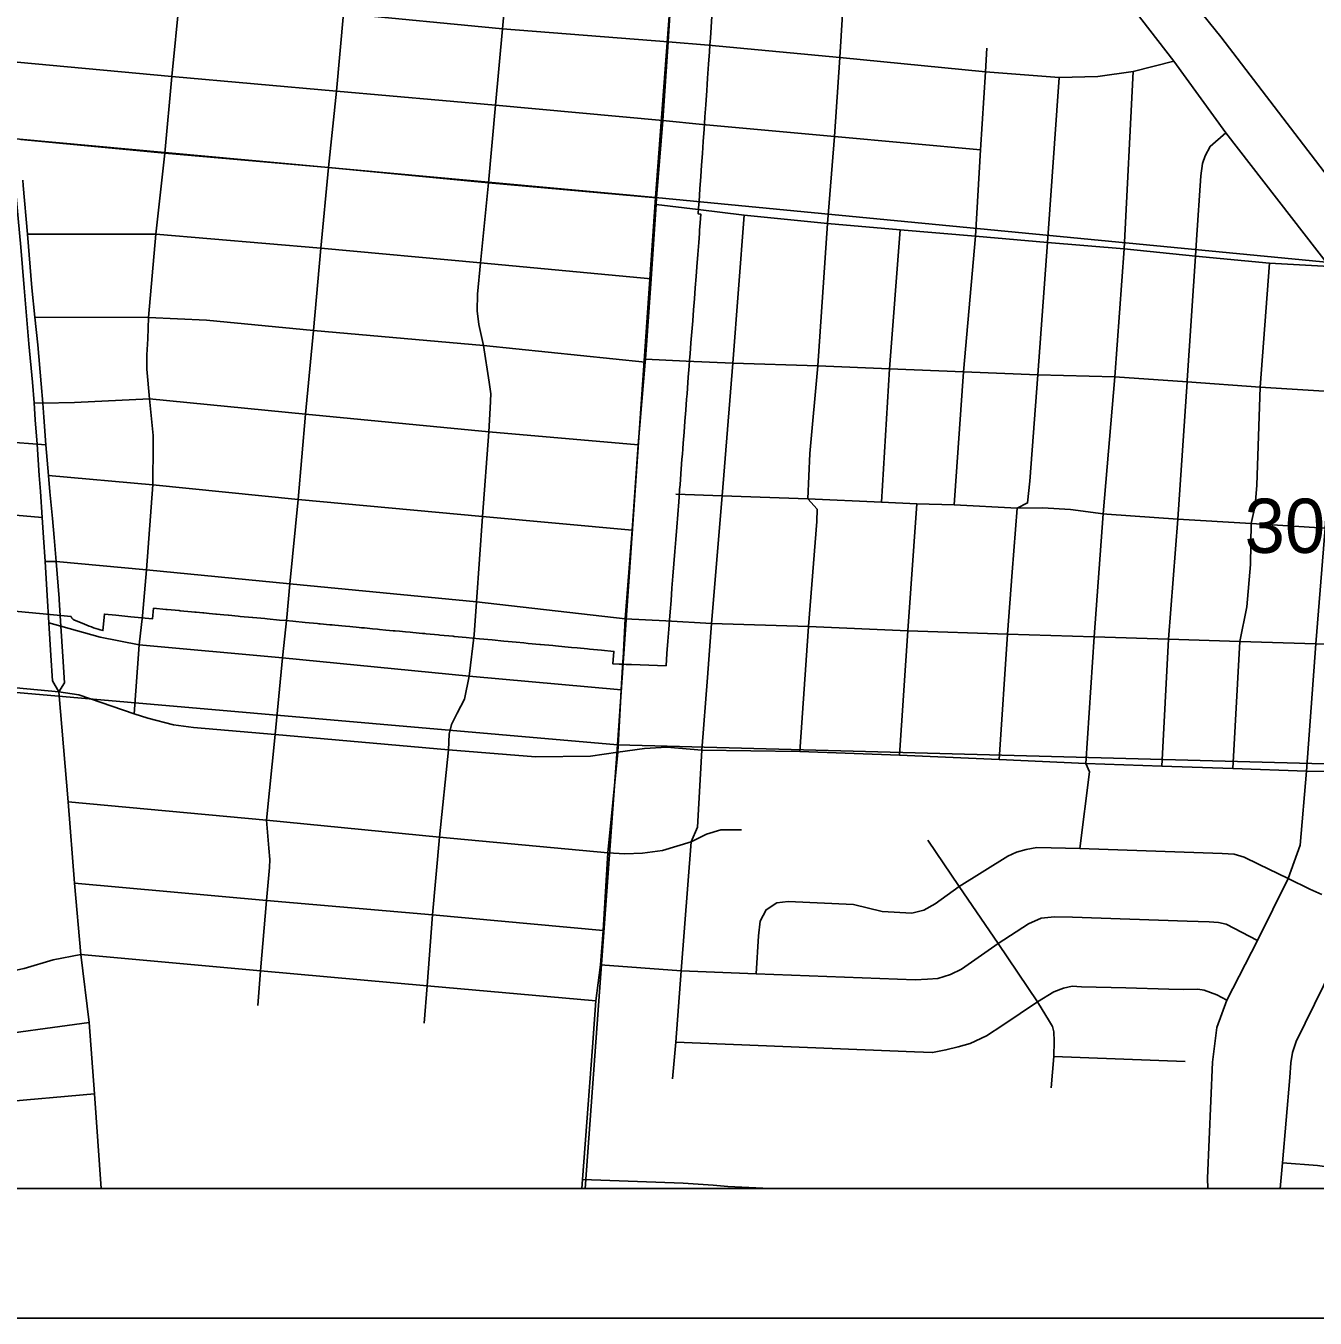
# Model space of a CAD drawing. Extents: x 0 to 34, y 0 to 22.
# Drawn here: x 7.342 to 8.337, y 14 to 14.998 of the extents above; entities that cross this region are included whole.
import ezdxf

# ---------------------------------------------------------------- set-up
doc = ezdxf.new("R2010")
doc.units = 0
for name, color, linetype in [('Default', 7, 'Continuous'), ('GM_X_City_Street', 7, 'Continuous'), ('GM_X_Corporation', 7, 'Continuous'), ('GM_X_Rail_Line', 7, 'Continuous'), ('GM_X_Section', 7, 'Continuous'), ('GM_X_Section_Text', 7, 'Continuous'), ('GM_X_State_Route', 7, 'Continuous'), ('GM_X_Township_Road', 7, 'Continuous'), ('SH_Data', 7, 'Continuous')]:
    doc.layers.add(name, color=color, linetype=linetype)

msp = doc.modelspace()

# ---------------------------------------------------------------- linework, layer by layer
at = {"layer": 'Default'}
for points in [[(8.9, 15.6028), (8.9, 15.78137), (7.90346, 15.87364), (7.82775, 14.86502), (8.83407, 14.76814)], [(6.72325, 14.1), (7.77344, 14.1), (7.79825, 14.44254), (6.76074, 14.53281), (6.76045, 14.51691)], [(7.77344, 14.1), (8.79639, 14.1), (8.82252, 14.41502), (7.79825, 14.44254)]]:
    msp.add_lwpolyline(points, close=True, dxfattribs=at)
at = {"layer": 'GM_X_City_Street'}
for p, q in [((7.8282, 14.85973), (7.86053, 14.85582)), ((7.34276, 14.83673), (7.37219, 14.83675)), ((7.81996, 14.74034), (7.85134, 14.73881)), ((8.1353, 14.20188), (8.23659, 14.19801)), ((7.26588, 14.16169), (7.39451, 14.17313))]:
    msp.add_line(p, q, dxfattribs=at)
for points in [[(7.80248, 14.50741), (7.8026, 14.50944), (7.80419, 14.53992), (7.80967, 14.60835), (7.81431, 14.67421), (7.81979, 14.73808), (7.81996, 14.74034), (7.82422, 14.80234), (7.8282, 14.85973), (7.82851, 14.86492), (7.83323, 14.92441), (7.83738, 14.98531), (7.84122, 15.04775), (7.84541, 15.10967), (7.85043, 15.17176), (7.85477, 15.23687), (7.86017, 15.30105), (7.86443, 15.36461), (7.86956, 15.42929), (7.87493, 15.48931), (7.87753, 15.51728)], [(7.93914, 14.43752), (7.94569, 14.53392), (7.95226, 14.61493), (7.95238, 14.62456), (7.94521, 14.63248), (7.94669, 14.66746), (7.95296, 14.73502), (7.96055, 14.8451), (7.96582, 14.91219), (7.96987, 14.97313), (7.97374, 15.03613), (7.97806, 15.09848), (7.98222, 15.16109), (7.98638, 15.22522), (7.99124, 15.26922), (7.99013, 15.27644), (7.97875, 15.29004), (7.92809, 15.36168)], [(8.44445, 14.41972), (8.451, 14.51656), (8.45794, 14.60152), (8.46058, 14.63262), (8.46002, 14.64178), (8.45781, 14.65066), (8.45392, 14.65899), (8.44656, 14.67093), (8.4168, 14.71819), (8.41047, 14.72742), (8.38701, 14.76102), (8.36285, 14.79392), (8.34798, 14.81194), (8.26805, 14.9151), (8.22792, 14.97021), (8.17045, 15.04462), (8.13972, 15.08425), (8.07356, 15.17136), (8.03941, 15.21703), (8.03261, 15.22771), (8.02817, 15.23813)], [(7.68756, 14.52761), (7.68949, 14.55294), (7.69418, 14.61878), (7.69893, 14.68431), (7.70014, 14.7025), (7.70057, 14.71355), (7.69927, 14.72257), (7.69491, 14.75076), (7.69118, 14.76702), (7.6901, 14.77766), (7.69025, 14.79044), (7.69258, 14.81472), (7.69868, 14.8765), (7.70421, 14.93624), (7.70959, 14.99525), (7.71526, 15.05775)], [(7.3291, 15.03094), (7.46012, 15.01847), (7.58683, 15.00705), (7.70959, 14.99525), (7.83738, 14.98531), (7.86862, 14.98272)], [(7.43159, 14.54219), (7.43472, 14.57776), (7.4395, 14.64325), (7.43978, 14.67471), (7.43983, 14.68129), (7.43712, 14.70967), (7.43498, 14.73253), (7.43489, 14.74356), (7.4356, 14.75609), (7.43627, 14.77249), (7.44185, 14.8368), (7.44885, 14.89925), (7.45437, 14.95858), (7.46012, 15.01847)], [(7.54291, 14.54077), (7.54529, 14.56689), (7.55185, 14.63199), (7.55747, 14.69793), (7.5636, 14.76251), (7.56928, 14.82608), (7.57526, 14.88819), (7.58146, 14.94729), (7.58683, 15.00705)], [(7.86862, 14.98272), (7.96987, 14.97313), (8.08245, 14.96216), (8.13922, 14.95773), (8.1692, 14.95841), (8.19655, 14.96244), (8.22792, 14.97021)], [(8.0583, 14.62791), (8.06537, 14.73062), (8.07481, 14.83512), (8.07856, 14.90178), (8.08245, 14.96216), (8.08342, 14.98048)], [(7.33473, 14.96963), (7.45437, 14.95858), (7.58146, 14.94729), (7.70421, 14.93624), (7.83323, 14.92441), (7.86384, 14.92148)], [(8.09288, 14.43134), (8.09938, 14.52808), (8.10299, 14.57584), (8.10686, 14.62534), (8.11493, 14.62928), (8.11659, 14.64622), (8.12284, 14.72825), (8.13036, 14.83045), (8.13922, 14.95773)], [(8.1552, 14.36244), (8.16265, 14.42185), (8.15985, 14.42807), (8.16629, 14.526), (8.17323, 14.62095), (8.18233, 14.72665), (8.18955, 14.8255), (8.19655, 14.96244)], [(7.86384, 14.92148), (7.96582, 14.91219), (8.07856, 14.90178)], [(8.21853, 14.42605), (8.22362, 14.5242), (8.23094, 14.61688), (8.238, 14.72285), (8.23807, 14.7239), (8.24446, 14.81984), (8.24529, 14.83241), (8.24873, 14.8818), (8.25003, 14.89128), (8.25202, 14.89733), (8.25593, 14.90449), (8.26805, 14.9151)], [(7.33779, 14.90977), (7.44885, 14.89925), (7.57526, 14.88819), (7.69868, 14.8765), (7.82851, 14.86492)], [(7.86053, 14.85582), (7.89618, 14.85146), (7.96055, 14.8451), (8.01664, 14.84008), (8.07481, 14.83512), (8.13036, 14.83045), (8.18955, 14.8255), (8.24446, 14.81984), (8.30164, 14.81445), (8.34798, 14.81194)], [(7.84082, 14.18468), (7.84344, 14.2131), (7.84738, 14.26806), (7.85518, 14.36757), (7.86007, 14.37911), (7.86355, 14.43838), (7.86793, 14.49462), (7.871, 14.53617), (7.87909, 14.63467), (7.88731, 14.73728), (7.89618, 14.85146)], [(7.37219, 14.83675), (7.44185, 14.8368), (7.56928, 14.82608), (7.69258, 14.81472), (7.82422, 14.80234)], [(8.00221, 14.62984), (8.00835, 14.73274), (8.01664, 14.84008)], [(8.27346, 14.42418), (8.27887, 14.52239), (8.28412, 14.54913), (8.28692, 14.5818), (8.28748, 14.61332), (8.29068, 14.62738), (8.29201, 14.6431), (8.29456, 14.71868), (8.30164, 14.81445)], [(8.33026, 14.42217), (8.33734, 14.52058), (8.34457, 14.60971), (8.35202, 14.71503), (8.35634, 14.76699), (8.35719, 14.78684), (8.35845, 14.78914), (8.36285, 14.79392)], [(7.34854, 14.77272), (7.43627, 14.77249), (7.4809, 14.77032), (7.5636, 14.76251), (7.69491, 14.75076), (7.81979, 14.73808)], [(7.85134, 14.73881), (7.88731, 14.73728), (7.95296, 14.73502), (8.00835, 14.73274), (8.06537, 14.73062), (8.12284, 14.72825), (8.18233, 14.72665), (8.238, 14.72285), (8.29456, 14.71868), (8.35202, 14.71503), (8.40756, 14.71299), (8.4168, 14.71819)], [(7.15465, 14.71039), (7.17396, 14.69747), (7.18437, 14.69271), (7.19427, 14.68932), (7.20744, 14.68631), (7.28905, 14.67941), (7.35032, 14.67462), (7.35688, 14.67411)], [(7.34802, 14.7065), (7.35464, 14.70645), (7.37916, 14.70681), (7.43712, 14.70967), (7.55747, 14.69793), (7.69893, 14.68431), (7.81431, 14.67421)], [(7.0696, 14.67518), (7.08051, 14.67263), (7.10461, 14.66403), (7.12338, 14.65579), (7.13702, 14.64782), (7.14746, 14.64269), (7.16434, 14.63613), (7.17764, 14.6339), (7.29483, 14.62324), (7.35419, 14.61804)], [(6.28784, 14.66728), (6.34893, 14.6487), (6.45161, 14.61893), (6.52667, 14.59923), (6.6213, 14.57436), (6.68486, 14.55652), (6.71161, 14.54761), (6.73821, 14.53567), (6.77373, 14.51453), (6.8255, 14.48246), (6.83873, 14.47599), (6.85613, 14.47081), (6.87641, 14.4688), (6.89223, 14.46894), (6.90273, 14.47081), (6.94645, 14.48218), (7.0132, 14.49983), (7.05128, 14.50431), (7.10536, 14.50327), (7.11039, 14.50312), (7.15983, 14.50073), (7.24783, 14.4934), (7.29805, 14.48994), (7.36696, 14.48349)], [(7.35905, 14.65061), (7.4395, 14.64325), (7.55185, 14.63199), (7.69418, 14.61878), (7.80967, 14.60835)], [(7.84326, 14.63595), (7.87909, 14.63467), (7.94521, 14.63248), (8.00221, 14.62984), (8.02942, 14.62859), (8.0583, 14.62791), (8.10686, 14.62534), (8.12645, 14.6254), (8.14811, 14.62428), (8.17323, 14.62095), (8.17622, 14.62074)], [(8.01608, 14.43465), (8.02248, 14.53059), (8.02942, 14.62859)], [(8.17622, 14.62074), (8.23094, 14.61688), (8.28748, 14.61332), (8.34457, 14.60971), (8.40117, 14.6061), (8.45794, 14.60152)], [(7.35652, 14.58408), (7.36498, 14.58406), (7.43472, 14.57776), (7.54529, 14.56689), (7.68949, 14.55294), (7.80419, 14.53992), (7.8356, 14.53829)], [(7.35919, 14.53675), (7.36865, 14.53412), (7.39892, 14.52568), (7.42903, 14.51972), (7.53969, 14.50972), (7.6838, 14.4955), (7.8012, 14.48504)], [(7.42529, 14.46657), (7.42903, 14.51972), (7.43159, 14.54219)], [(7.52074, 14.24131), (7.52263, 14.26814), (7.52744, 14.32237), (7.52977, 14.34789), (7.52992, 14.35401), (7.52919, 14.36276), (7.52729, 14.38448), (7.53413, 14.45062), (7.53969, 14.50972), (7.54291, 14.54077)], [(7.8356, 14.53829), (7.871, 14.53617), (7.94569, 14.53392), (8.02248, 14.53059), (8.09938, 14.52808), (8.16629, 14.526), (8.22362, 14.5242), (8.27887, 14.52239), (8.33734, 14.52058), (8.39508, 14.5182), (8.451, 14.51656)], [(7.64911, 14.22768), (7.65136, 14.25648), (7.65552, 14.31129), (7.66099, 14.37136), (7.66793, 14.43873), (7.66835, 14.45074), (7.6701, 14.45832), (7.67447, 14.46693), (7.68029, 14.47772), (7.6838, 14.4955), (7.68756, 14.52761)], [(7.7709, 14.1), (7.77134, 14.10712), (7.77893, 14.20921), (7.78162, 14.24488), (7.78517, 14.27282), (7.78714, 14.29934), (7.79088, 14.35926), (7.79868, 14.437), (7.8012, 14.48504), (7.80248, 14.50741)], [(7.36696, 14.48349), (7.38247, 14.48117), (7.42529, 14.46657), (7.43582, 14.46312), (7.45545, 14.45809), (7.47101, 14.45602), (7.53413, 14.45062), (7.66793, 14.43873), (7.73504, 14.43324), (7.77736, 14.43378), (7.79868, 14.437), (7.81921, 14.43982), (7.83647, 14.44083), (7.86355, 14.43838), (7.93914, 14.43752), (8.01608, 14.43465), (8.09288, 14.43134), (8.15985, 14.42807), (8.21853, 14.42605), (8.27346, 14.42418), (8.33026, 14.42217), (8.38727, 14.42121)], [(8.254, 14.1), (8.25371, 14.10816), (8.25761, 14.19764), (8.26105, 14.22448), (8.26885, 14.24559), (8.29246, 14.29148), (8.31611, 14.33944), (8.32529, 14.36513), (8.33026, 14.42217)], [(7.37427, 14.39866), (7.52729, 14.38448), (7.66099, 14.37136), (7.79088, 14.35926), (7.80407, 14.35839), (7.81764, 14.3589), (7.83316, 14.36101), (7.85518, 14.36757), (7.86699, 14.37369), (7.87821, 14.3769), (7.89396, 14.3769)], [(8.13313, 14.17792), (8.1353, 14.20188), (8.13545, 14.21393), (8.1353, 14.22103), (8.13414, 14.22505), (8.1319, 14.2291), (8.12247, 14.24429), (8.09227, 14.2891), (8.06214, 14.33314), (8.03803, 14.36899)], [(7.90538, 14.26567), (7.90708, 14.29516), (7.90842, 14.30654), (7.91307, 14.31531), (7.9213, 14.32051), (7.93006, 14.32174), (7.98049, 14.31941), (8.00255, 14.31393), (8.02557, 14.3127), (8.03489, 14.31503), (8.04352, 14.31983), (8.06214, 14.33314), (8.09956, 14.35669), (8.10641, 14.3597), (8.11395, 14.36176), (8.12204, 14.36326), (8.1552, 14.36244), (8.26522, 14.3586), (8.27441, 14.35806), (8.28211, 14.35585), (8.29318, 14.35052), (8.31611, 14.33944), (8.33292, 14.33107), (8.34196, 14.32695)], [(6.95974, 14.35435), (7.00345, 14.33709), (7.0222, 14.32622), (7.02923, 14.32059), (7.0341, 14.31415), (7.03917, 14.30746), (7.0463, 14.30146), (7.05324, 14.29733), (7.06169, 14.29433), (7.07303, 14.29321), (7.10388, 14.29208), (7.11448, 14.29133), (7.12705, 14.28899), (7.13774, 14.28617), (7.15369, 14.28157), (7.17936, 14.2713), (7.20653, 14.26364), (7.23012, 14.25982), (7.26407, 14.25907), (7.30927, 14.26357), (7.34022, 14.26995), (7.36254, 14.27651), (7.3839, 14.2808)], [(7.37917, 14.33579), (7.52744, 14.32237), (7.65552, 14.31129), (7.78714, 14.29934)], [(8.30992, 14.1), (8.31168, 14.11991), (8.31743, 14.18582), (8.31812, 14.19719), (8.31935, 14.205), (8.32223, 14.2135), (8.36457, 14.29941), (8.36813, 14.32284)], [(7.78517, 14.27282), (7.84738, 14.26806), (7.90538, 14.26567), (8.02818, 14.26122), (8.03764, 14.2616), (8.04567, 14.26217), (8.05551, 14.26519), (8.06391, 14.26938), (8.09227, 14.2891), (8.11563, 14.30442), (8.12546, 14.30868), (8.13576, 14.30991), (8.14957, 14.30953), (8.23805, 14.3065), (8.25498, 14.30594), (8.26225, 14.30537), (8.26821, 14.30423), (8.29246, 14.29148)], [(7.3839, 14.2808), (7.52263, 14.26814), (7.65136, 14.25648), (7.78162, 14.24488)], [(7.84344, 14.2131), (8.0276, 14.20551), (8.04151, 14.20505), (8.05186, 14.20705), (8.06144, 14.20937), (8.07056, 14.21207), (8.08315, 14.21795), (8.09574, 14.22629), (8.12247, 14.24429), (8.13507, 14.25187), (8.14256, 14.25472), (8.14944, 14.25626), (8.15647, 14.25588), (8.19077, 14.25503), (8.22384, 14.25387), (8.23496, 14.25372), (8.2464, 14.25395), (8.25119, 14.25318), (8.261, 14.24947), (8.26885, 14.24559)], [(6.97034, 14.2325), (6.99724, 14.21666), (7.01866, 14.20941), (7.0267, 14.20815), (7.04583, 14.20784), (7.0741, 14.20862), (7.09969, 14.20902), (7.12662, 14.20752), (7.14662, 14.20571), (7.16559, 14.20146), (7.20224, 14.19501), (7.23115, 14.19182), (7.24672, 14.19117), (7.25666, 14.19201), (7.26023, 14.19276), (7.26276, 14.19492), (7.26848, 14.20111), (7.27185, 14.20683), (7.27401, 14.20964), (7.27786, 14.21152), (7.28836, 14.21443), (7.30356, 14.21649), (7.39034, 14.22813)], [(8.31168, 14.11991), (8.33881, 14.11772), (8.35155, 14.11593), (8.3606, 14.11319), (8.3717, 14.10744), (8.38708, 14.1)], [(7.77134, 14.10712), (7.84897, 14.10422), (7.8723, 14.10254)], [(7.8723, 14.10254), (7.88346, 14.10174), (7.91599, 14.1)]]:
    msp.add_lwpolyline(points, dxfattribs=at)
at = {"layer": 'GM_X_Corporation'}
msp.add_lwpolyline([(7.87122, 15.0051), (7.87063, 14.99654), (7.87004, 14.98796), (7.8697, 14.98305), (7.86932, 14.97757), (7.86866, 14.96812), (7.86791, 14.95716), (7.86758, 14.95243), (7.86725, 14.94771), (7.86649, 14.93674), (7.86584, 14.9273), (7.86547, 14.92198), (7.86519, 14.91785), (7.86453, 14.9084), (7.86388, 14.89895), (7.86327, 14.8901), (7.86265, 14.88125), (7.862, 14.8718), (7.86132, 14.8619), (7.86098, 14.85708), (7.86066, 14.85244), (7.86186, 14.85231), (7.86277, 14.85221), (7.86219, 14.84554), (7.86175, 14.83987), (7.86156, 14.83732), (7.86102, 14.83043), (7.86029, 14.82098), (7.85957, 14.81153), (7.85898, 14.80398), (7.85833, 14.79548), (7.85767, 14.78697), (7.85702, 14.77847), (7.85636, 14.76997), (7.8557, 14.76147), (7.85505, 14.75297), (7.85438, 14.74429), (7.85401, 14.73955), (7.85365, 14.73485), (7.85299, 14.72635), (7.85234, 14.71785), (7.85201, 14.71361), (7.85168, 14.70935), (7.85103, 14.70086), (7.85037, 14.69236), (7.84972, 14.68386), (7.84906, 14.67536), (7.84873, 14.67111), (7.8484, 14.66687), (7.84811, 14.66309), (7.84782, 14.65931), (7.84724, 14.65176), (7.84665, 14.64326), (7.8463, 14.63959), (7.84587, 14.63401), (7.84556, 14.63003), (7.84481, 14.62028), (7.84407, 14.61065), (7.84334, 14.60121), (7.84261, 14.59177), (7.84188, 14.58233), (7.84108, 14.57289), (7.84036, 14.56345), (7.83964, 14.55401), (7.83897, 14.54515), (7.83849, 14.53881), (7.83796, 14.53192), (7.83724, 14.52248), (7.83653, 14.51304), (7.83581, 14.5036), (7.80904, 14.50456), (7.80809, 14.50459), (7.80494, 14.50471), (7.80235, 14.5048), (7.80139, 14.50483), (7.79959, 14.5049), (7.7949, 14.50507), (7.79483, 14.50507), (7.79558, 14.51471), (7.78604, 14.51561), (7.78592, 14.51562), (7.77661, 14.51649), (7.77509, 14.51664), (7.76718, 14.51737), (7.76283, 14.51779), (7.75775, 14.51826), (7.75057, 14.51894), (7.74833, 14.51914), (7.7389, 14.52003), (7.73832, 14.52008), (7.72947, 14.52091), (7.72606, 14.52123), (7.72004, 14.5218), (7.7138, 14.52238), (7.71061, 14.52268), (7.70154, 14.52353), (7.69174, 14.52445), (7.68626, 14.52496), (7.68137, 14.52542), (7.6721, 14.52629), (7.67137, 14.52636), (7.66113, 14.52732), (7.66006, 14.52742), (7.65063, 14.5283), (7.64966, 14.5284), (7.6478, 14.52857), (7.64026, 14.52928), (7.6382, 14.52947), (7.6346, 14.52981), (7.62989, 14.53025), (7.62673, 14.53055), (7.62598, 14.53062), (7.62517, 14.53069), (7.61952, 14.53122), (7.61451, 14.53169), (7.61292, 14.53184), (7.60915, 14.5322), (7.60305, 14.53277), (7.60066, 14.53299), (7.59878, 14.53317), (7.59158, 14.53384), (7.5884, 14.53414), (7.58012, 14.53492), (7.57803, 14.53511), (7.57615, 14.53529), (7.56865, 14.53599), (7.56766, 14.53609), (7.56672, 14.53617), (7.55719, 14.53707), (7.54776, 14.53795), (7.54224, 14.53847), (7.53739, 14.53893), (7.52787, 14.53982), (7.52598, 14.54), (7.51667, 14.54087), (7.51656, 14.54088), (7.50713, 14.54176), (7.50549, 14.54192), (7.49808, 14.54261), (7.4977, 14.54265), (7.49427, 14.54297), (7.48884, 14.54348), (7.48827, 14.54353), (7.48309, 14.54402), (7.47884, 14.54442), (7.47828, 14.54447), (7.47304, 14.54496), (7.47192, 14.54507), (7.46941, 14.5453), (7.46074, 14.54611), (7.45999, 14.54619), (7.45056, 14.54707), (7.44956, 14.54716), (7.44019, 14.54804), (7.43944, 14.53988), (7.42247, 14.54151), (7.41112, 14.5426), (7.40217, 14.54346), (7.40103, 14.53074), (7.39892, 14.53135), (7.39749, 14.53176), (7.39569, 14.53233), (7.39389, 14.53294), (7.39211, 14.53358), (7.39033, 14.53424), (7.38857, 14.53494), (7.38682, 14.53567), (7.37864, 14.53904), (7.37849, 14.53912), (7.37836, 14.5392), (7.37823, 14.53928), (7.37811, 14.53937), (7.37799, 14.53946), (7.37787, 14.53956), (7.37775, 14.53966), (7.37764, 14.53976), (7.37753, 14.53987), (7.37743, 14.53998), (7.37733, 14.54009), (7.37724, 14.54021), (7.37714, 14.54033), (7.37706, 14.54046), (7.37697, 14.54059), (7.37689, 14.54072), (7.37682, 14.54085), (7.37675, 14.54098), (7.37669, 14.54112), (7.37663, 14.54126), (7.37657, 14.5414), (7.37652, 14.54155), (7.3765, 14.54163), (7.35196, 14.54403), (7.3275, 14.54634)], dxfattribs=at)
at = {"layer": 'GM_X_Rail_Line'}
msp.add_lwpolyline([(7.76631, 16.17032), (7.77508, 16.13743), (7.77946, 16.09192), (7.77995, 16.01841), (7.7813, 15.93269), (7.78495, 15.88796), (7.79153, 15.83313), (7.80572, 15.75059), (7.81784, 15.70483), (7.83045, 15.65987), (7.8458, 15.61546), (7.85731, 15.58147), (7.89573, 15.50605), (7.93121, 15.43418), (7.96441, 15.38435), (8.01081, 15.32124), (8.167, 15.10939), (8.26419, 14.98904), (8.42963, 14.77298)], dxfattribs=at)
at = {"layer": 'GM_X_Section'}
for points in [[(6.90635, 15.9571), (7.90346, 15.87364), (7.82775, 14.86502), (6.81453, 14.95787)], [(6.79602, 14.96048), (6.81453, 14.95787), (7.82775, 14.86502), (7.79825, 14.44254), (6.76074, 14.53281)], [(7.82775, 14.86502), (8.83407, 14.76814), (8.82252, 14.41502), (7.79825, 14.44254)]]:
    msp.add_lwpolyline(points, close=True, dxfattribs=at)
at = {"layer": 'GM_X_State_Route'}
for points in [[(7.35919, 14.53675), (7.35794, 14.55787), (7.35652, 14.58408), (7.35528, 14.60252), (7.35419, 14.61804), (7.35283, 14.63814), (7.35195, 14.65038), (7.35032, 14.67462), (7.3488, 14.69344), (7.34802, 14.7065), (7.34656, 14.72261), (7.34395, 14.75224), (7.34203, 14.77369), (7.34032, 14.7954), (7.33758, 14.82668), (7.3356, 14.84881), (7.33325, 14.87448), (7.3323, 14.88211)], [(7.36723, 14.55458), (7.36716, 14.5556), (7.36498, 14.58406), (7.36341, 14.60267), (7.36206, 14.61725), (7.36013, 14.63788), (7.35905, 14.65061), (7.35688, 14.67411), (7.35531, 14.69551), (7.35464, 14.70645), (7.35349, 14.72129), (7.35068, 14.75139), (7.34854, 14.77272), (7.34625, 14.79544), (7.34276, 14.83673), (7.3395, 14.87439), (7.33927, 14.87854)], [(7.36696, 14.48349), (7.37127, 14.49035), (7.37008, 14.51087), (7.36865, 14.53412), (7.36723, 14.55458)], [(7.36696, 14.48349), (7.36203, 14.49192), (7.36085, 14.51142), (7.35919, 14.53675)], [(7.3996, 14.1), (7.39451, 14.17313), (7.39034, 14.22813), (7.3839, 14.2808), (7.37917, 14.33579), (7.37427, 14.39866), (7.36696, 14.48349)]]:
    msp.add_lwpolyline(points, dxfattribs=at)
at = {"layer": 'GM_X_Township_Road'}
msp.add_lwpolyline([(3.92512, 14.1), (8.9, 14.1), (8.9, 20.9)], dxfattribs=at)
at = {"layer": 'SH_Data'}
for p, q in [((2.1, 14.1), (8.9, 14.1)), ((2, 14), (9, 14))]:
    msp.add_line(p, q, dxfattribs=at)

# ---------------------------------------------------------------- texts
at = {"layer": 'GM_X_Section_Text'}
msp.add_text('30', height=0.041856, rotation=0.00001, dxfattribs=at).set_placement((8.28243, 14.59075))

doc.saveas('drawing.dxf')
